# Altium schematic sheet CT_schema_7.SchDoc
size 277 x 170 mm
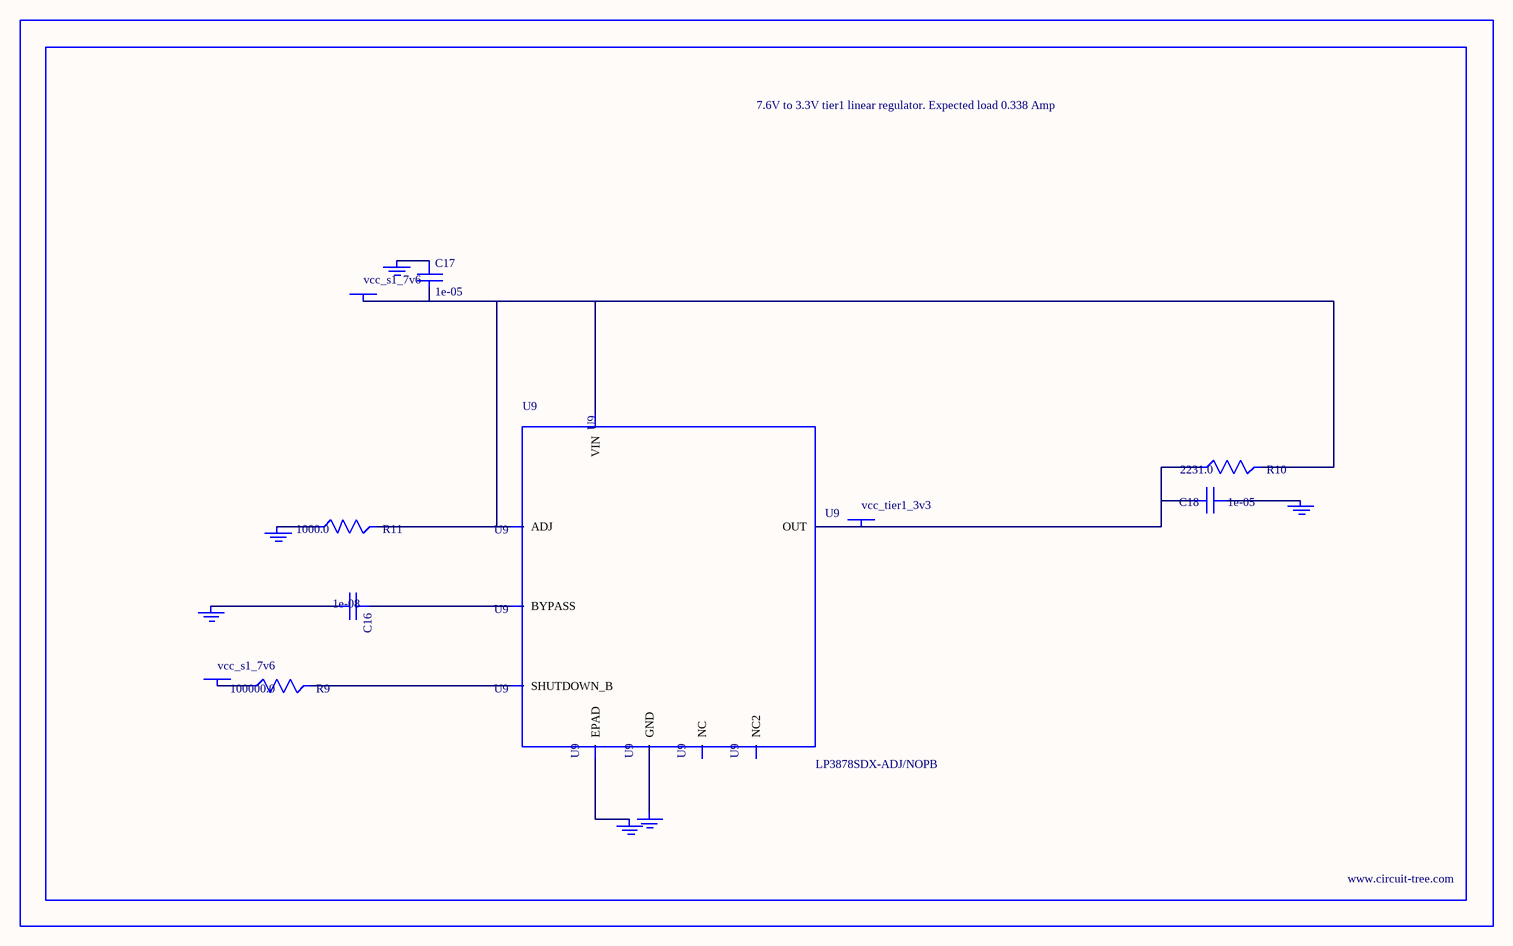
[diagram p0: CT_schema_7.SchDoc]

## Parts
BORDER6  (no value)
C16  1e-08  [C0402]
C17  1e-05  [C1206]
C18  1e-05  [C1210]
GND_INSTANCE_6_0  (no value)
GND_INSTANCE_6_1  (no value)
GND_INSTANCE_6_2  (no value)
GND_INSTANCE_6_3  (no value)
GND_INSTANCE_6_4  (no value)
GND_INSTANCE_6_5  (no value)
POWER_INSTANCE_6_0  vcc_s1_7v6
POWER_INSTANCE_6_1  vcc_s1_7v6
POWER_INSTANCE_6_2  vcc_tier1_3v3
R9  100000.0  [R0603]
R10  2231.0  [R0603]
R11  1000.0  [R0603]
U9  LP3878SDX-ADJ/NOPB  [WSON-8]

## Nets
NetC16_1: C16.1 U9.1(BYPASS)
NetC16_2: C16.2 GND_INSTANCE_6_0.0(GND)
NetC17_1: C17.1 GND_INSTANCE_6_1.0(GND)
NetC17_2: C17.2 POWER_INSTANCE_6_0.0(PWR) R10.2 R11.2 U9.4(VIN) U9.6(ADJ)
NetC18_1: C18.1 GND_INSTANCE_6_2.0(GND)
NetC18_2: C18.2 POWER_INSTANCE_6_2.0(PWR) R10.1 U9.5(OUT)
NetGND_INSTANCE_6_3_0: GND_INSTANCE_6_3.0(GND) R11.1
NetGND_INSTANCE_6_4_0: GND_INSTANCE_6_4.0(GND) U9.PAD(EPAD)
NetGND_INSTANCE_6_5_0: GND_INSTANCE_6_5.0(GND) U9.3(GND)
NetPOWER_INSTANCE_6_1_0: POWER_INSTANCE_6_1.0(PWR) R9.1
NetR9_2: R9.2 U9.8(SHUTDOWN_B)

Not connected (* = marked no-connect by the designer): U9 2(NC) 7(NC2)

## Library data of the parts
BORDER6 = BORDER_PAGE6
C16 = C0402C103K3RAC
C17 = C1206C106K3RACTU
C18 = GRM32DR61E106MA12L
GND_INSTANCE_6_0-GND_INSTANCE_6_5 = GND
POWER_INSTANCE_6_0-POWER_INSTANCE_6_2 = PWR
R9 = RC0603JR-07100KL
R10 = R10
R11 = RC0603JR-071KL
